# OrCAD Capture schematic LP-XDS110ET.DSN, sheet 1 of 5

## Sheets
1 1_Debugger Interface: size A3; title: LP-XDS110ET; rev: B; company: Texas Instruments
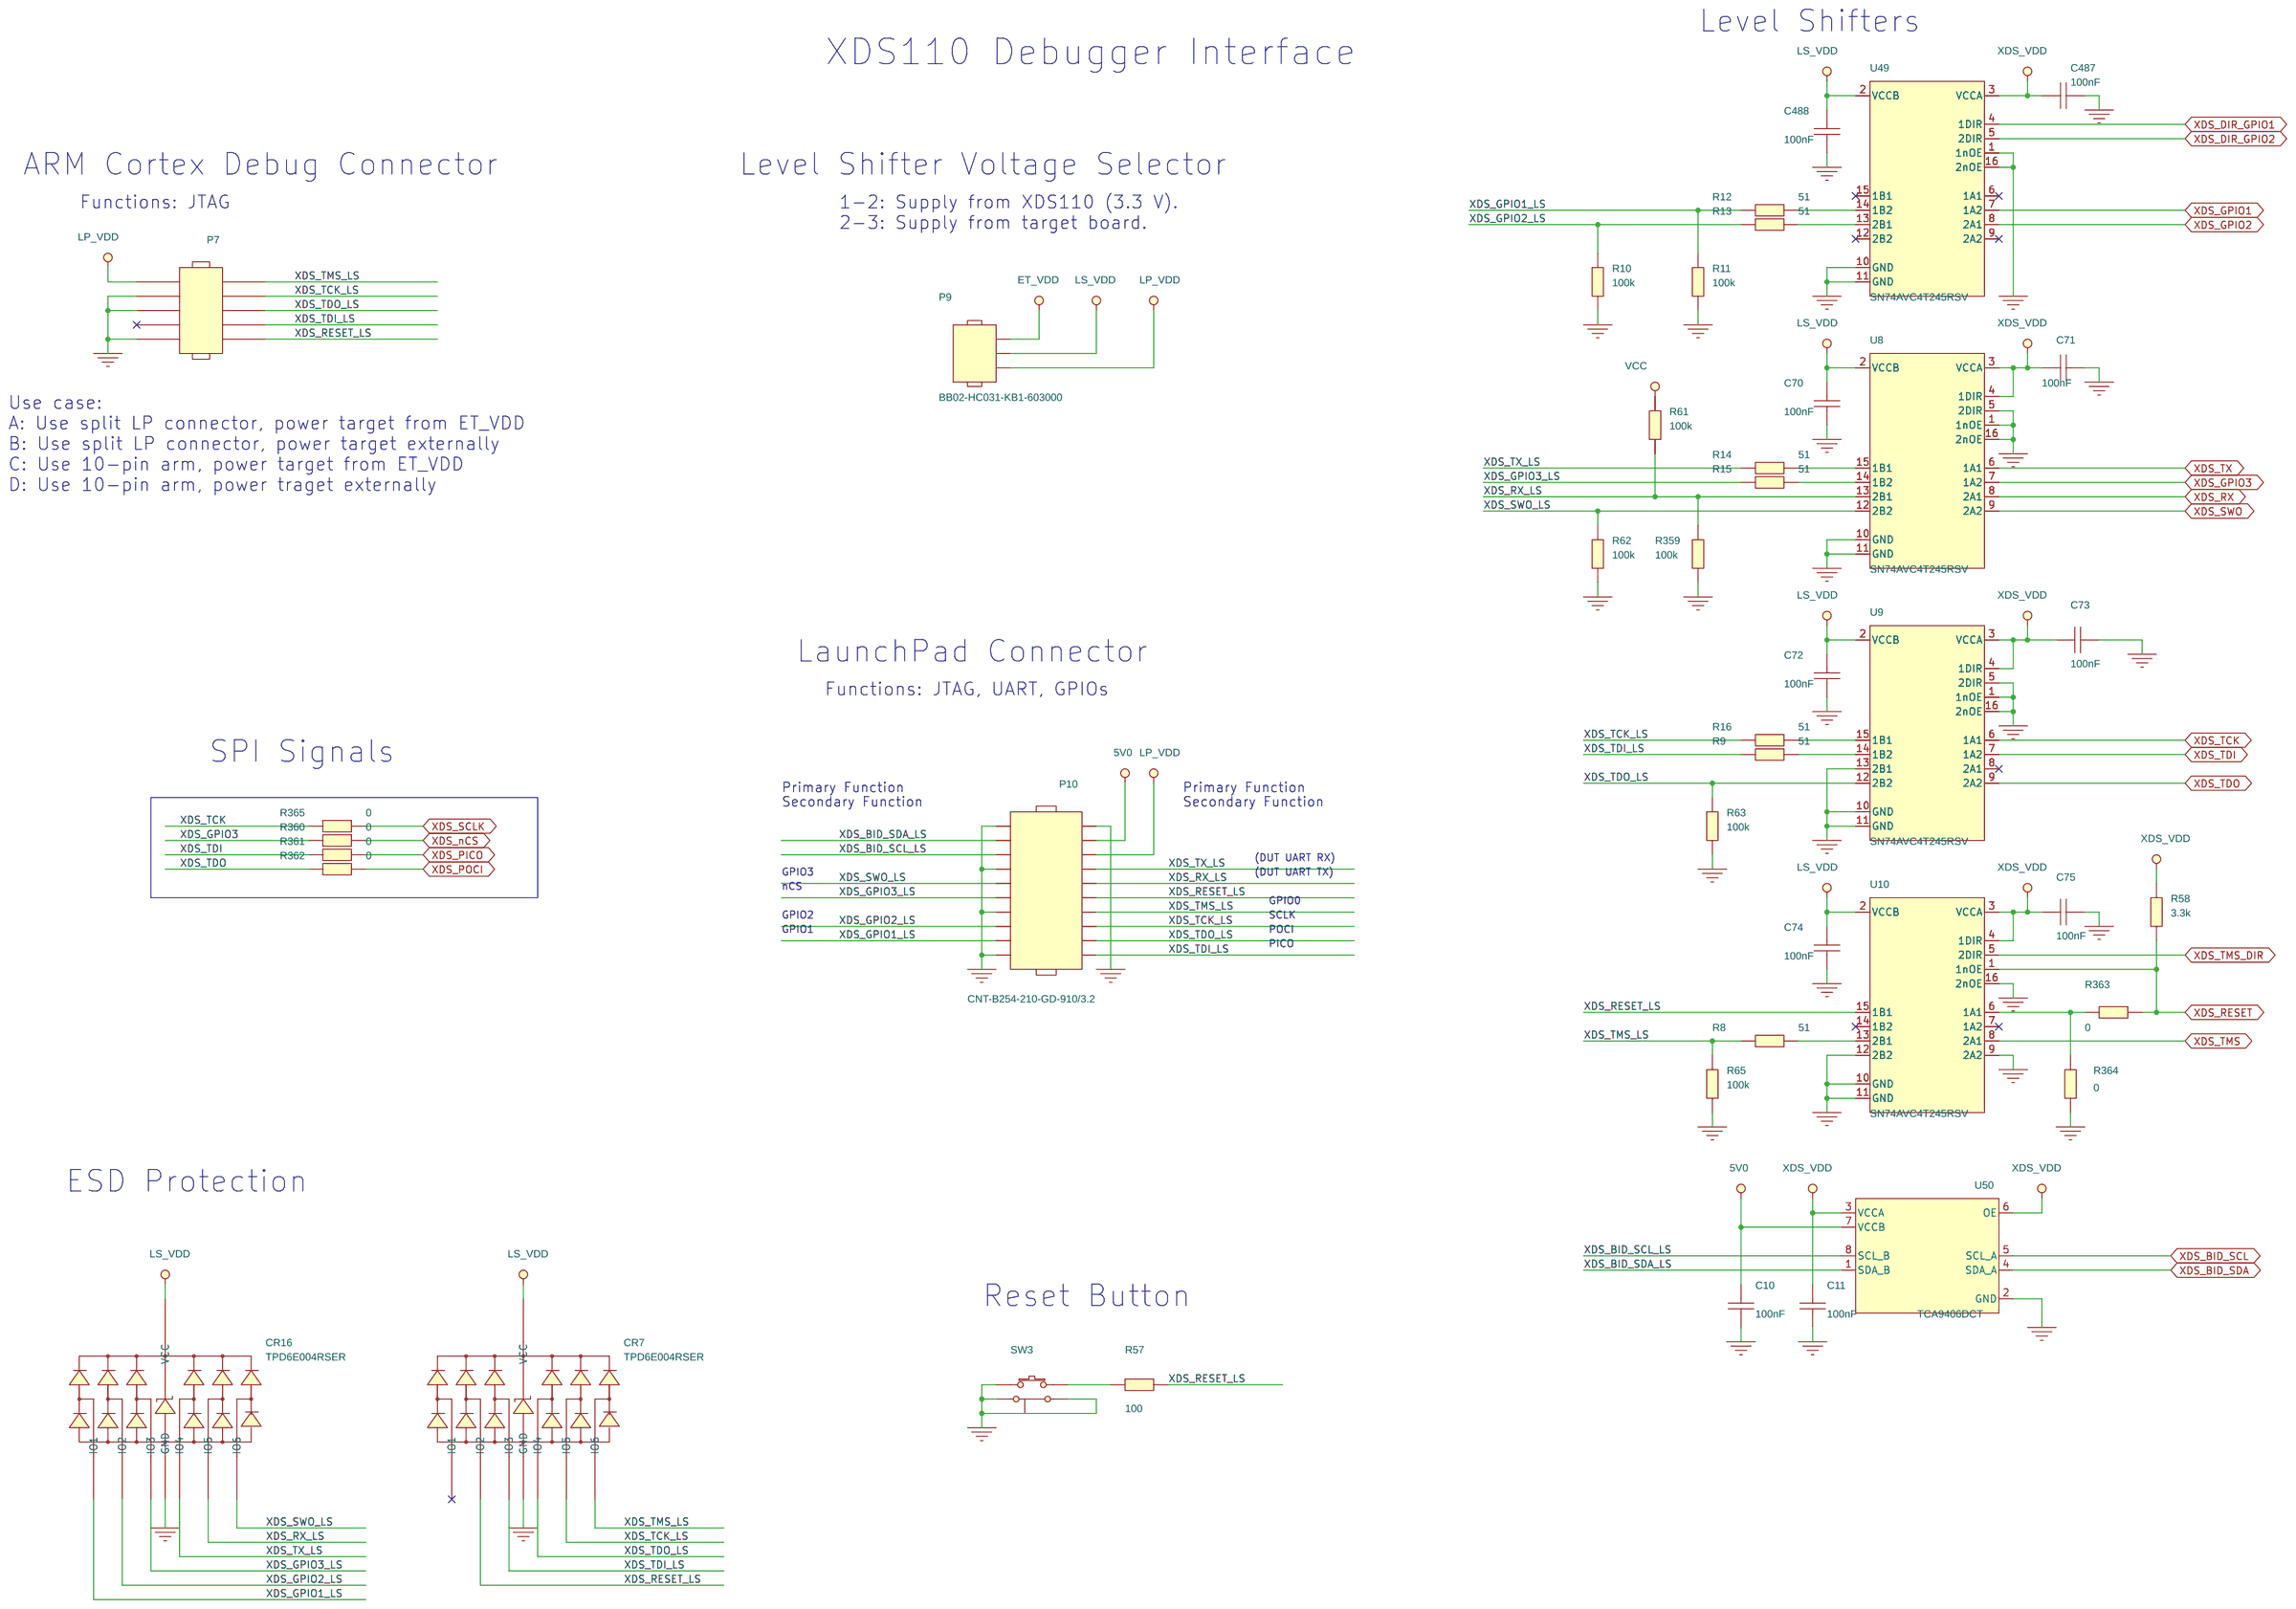
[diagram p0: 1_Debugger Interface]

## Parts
C10  100nF  [CAPC0603X35B2N]
C11  100nF  [CAPC0603X35B2N]
C70  100nF  [CAPC0603X35B2N]
C71  100nF  [CAPC0603X35B2N]
C72  100nF  [CAPC0603X35B2N]
C73  100nF  [CAPC0603X35B2N]
C74  100nF  [CAPC0603X35B2N]
C75  100nF  [CAPC0603X35B2N]
C487  100nF  [CAPC0603X35B2N]
C488  100nF  [CAPC0603X35B2N]
CR7  TPD6E004RSER  [QFN50P150X150X60-8N]
CR16  TPD6E004RSER  [QFN50P150X150X60-8N]
P7  FTSH-105-01-F-DV-K  [SAMTEC_FTSH-105-01-F-DV-K-10L]
P9  BB02-HC031-KB1-603000  [GRADCONN_BB02HC031KB1603000_A2B]
P10  CNT-B254-210-GD-910/3.2  [CNT_CNTB254210GD91032_A2B]
R8  51  [RESC0603X35B2N]
R9  51  [RESC0603X35B2N]
R10  100k  [RESC1005X40B2N]
R11  100k  [RESC1005X40B2N]
R12  51  [RESC0603X35B2N]
R13  51  [RESC0603X35B2N]
R14  51  [RESC0603X35B2N]
R15  51  [RESC0603X35B2N]
R16  51  [RESC0603X35B2N]
R57  100  [RESC1005X40B2N]
R58  3.3k  [RESC1005X40B2N]
R61  100k  [RESC1005X40B2N]
R62  100k  [RESC1005X40B2N]
R63  100k  [RESC1005X40B2N]
R65  100k  [RESC1005X40B2N]
R359  100k  [RESC1005X40B2N]
R360  0  [RESC1005X40B2N]
R361  0  [RESC1005X40B2N]
R362  0  [RESC1005X40B2N]
R363  0  [RESC1005X40B2N]
R364  0  [RESC1005X40B2N]
R365  0  [RESC1005X40B2N]
SW3  1188E-1K2  [SW_1188E1K2V_A2N]
U8  SN74AVC4T245RSV  [QFNFC40P180X260X55-16A2N]
U9  SN74AVC4T245RSV  [QFNFC40P180X260X55-16A2N]
U10  SN74AVC4T245RSV  [QFNFC40P180X260X55-16A2N]
U49  SN74AVC4T245RSV  [QFNFC40P180X260X55-16A2N]
U50  TCA9406DCT  [SOP65P400X130-8A2N]

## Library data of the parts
C10 C11 C70-C75 C487 C488 = CAPACITOR: CAPACITOR, CERAMIC X5R, 100nF, 10V, -10%/+10%, -55DEGC/+85DEGC, 0201, SMD; ALT_SYMBOLS: CAPC0603X35B2L,CAPC0603X35B2M; Additional Datasheet URL: http://psearch.en.murata.com/capacitor/product/GRM033R61A104KE84%23.html; AutoDoc File: https://notefied-dynamic-precision.com/DB/Apps/Desktop/Item/Object.aspx?id=96679; BU Name: DYNAMIC PRECISION GDANSK; Budget Currency: EUR; Budget Price: 0.008; Budgetary Price: 0.008 EUR; Client Status: UNDER_REVIEW; Country of Origin: Missing Info; Datasheet URL: http://psearch.murata.com/capacitor/product/GRM033R61A104KE84%23.pdf; Datasheet URL 1: http://psearch.murata.com/capacitor/product/GRM033R61A104KE84%23.pdf; Datasheet URL 2: http://search.murata.co.jp/Ceramy/image/img/w_hinm/L0005E.pdf; Dielectric Type: X5R; Lead Time: 17; LifeCycle Status: ACTIVE; MPN: GRM155R70J104KA01D; MPN Status: ACTIVE; Manufacturer: MURATA; Mass: 0.00033g; Max Oper Temp: +85DEGC; Max Tol: +10%; Maximum Operating Temperature: +85DEGC; Maximum Tolerance: +10%; Min Oper Temp: -55DEGC; Min Tol: -10%; Minimum Operating Temperature: -55DEGC; Minimum Tolerance: -10%; Mounting Type: SMD; NOTE Status: PREFERRED; NOTEfied URL: https://notefied-dynamic-precision.com/NOTEfiedWebInterface/part/show?partNumber=02-06085; Old Footprint: CAPC1005X60N,0402; PCB Package: 0201; Packing Size: 15000; Packing Type: Tape & Reel; Part Number: 02-06085; Part Type: Capacitor|CERAMIC|0201|STANDARD; REACH/SVHC Compliance: Compliant; REACH/SVHC Details: SVHC List Version Jul 7, 2017; REACH/SVHC Source: REACH Declaration; REACH/SVHC Status: Unaffected; REACH/SVHC_COMPLIANCE: COMPLIANT; REACH/SVHC_DETAILS: SVHC LIST VERSION Jun 20, 2016; REACH/SVHC_SOURCE: REACH DECLARATION; REACH/SVHC_STATUS: UNAFFECTED; ROHS: Compliant; Rated Voltage: 10V; Revision: R011; RoHS Status: ROHS_COMPLIANT; Rtd Voltage: 10V; Status: Released; Texas Part Status: Under Review; Type: Capacitor; Vendor: MURATA; Vendor Part Number: GRM033R61A104KE84D; Vendor Part Status: Active; WEIGHT: 0.00033g
CR7 CR16 = DIODE_TVS_TPD6E004_QFN8_V1: DIODE, PROTECTION, ESD ARRAY - 6 CHANNELS, 7V, -40DEGC/+85DEGC, QFN8, SMD; ALT_SYMBOLS: QFN50P150X150X60-8L,QFN50P150X150X60-8M; Additional Datasheet URL: http://www.ti.com/litv/pdf/mpqf207d; AutoDoc File: https://notefied-dynamic-precision.com/DB/Apps/Desktop/Item/Object.aspx?id=74721; BU Name: DYNAMIC PRECISION GDANSK; Budget Currency: USD; Budget Price: 0.27; Budgetary Price: 0.27 USD; CLASS: IC; Client Status: UNDER_REVIEW; Country of Origin: United States; Datasheet URL: http://www.ti.com/lit/ds/symlink/tpd6e004.pdf; Datasheet URL 1: http://www.ti.com/lit/ds/symlink/tpd6e004.pdf; Datasheet URL 2: http://www.ti.com/litv/pdf/mpqf207b; FPLIST: QFN50P150X150X60-8N,QFN50P150X150X60-8AN; Lead Time: 2; Mass: 0.0033g; Max Oper Temp: +85DEGC; Maximum Operating Temperature: +85DEGC; Min Oper Temp: -40DEGC; Minimum Operating Temperature: -40DEGC; Mounting Type: SMD; NOTEfied URL: https://notefied-dynamic-precision.com/NOTEfiedWebInterface/part/show?partNumber=14-05493; PCB Package: QFN8; Packing Size: 3000; Packing Type: Tape & Reel; Part Number: 14-05493; Part Type: Diode|PROTECTION; REACH/SVHC Compliance: Compliant; REACH/SVHC Details: SVHC List Version Jun 20, 2016; REACH/SVHC Source: Material Declaration; REACH/SVHC Status: Unaffected; ROHS: Compliant; Rated Power: N/A; Rated Voltage: 7V; Revision: R006; RoHS Status: ROHS_COMPLIANT; Rtd Power: N/A; Rtd Voltage: 7V; Status: Released; Texas Part Status: Under Review; Type: Diode; Vendor: TEXAS INSTRUMENTS; Vendor Part Status: Active; Weight: 0.0033g
P7 = CONN_HEADER_2X5: CONNECTOR, HEADER, MALE, STRAIGHT, 2 ROWS, 10 PINS, PITCH 1.27mm, SMD; ALT_SYMBOLS: SAMTEC_FTSH10501FDVK_A2L,SAMTEC_FTSH10501FDVK_A2M; Additional Datasheet URL: http://suddendocs.samtec.com/prints/ftsh-1xx-xx-xxx-dv-xxx-xxx-mkt.pdf; AutoDoc File: http://notefied-dynamic-precision.com/DB/Apps/Desktop/Item/Object.aspx?id=50836; Budget Currency: USD; Budget Price: 1.700; Budgetary Price: 1.7 USD; CLASS: IO; Country of Origin: China,Costa Rica,Malaysia,Singapore,United States; Datasheet URL: http://suddendocs.samtec.com/catalog_english/ftsh_smt.pdf; Datasheet URL 1: http://www.samtec.com/documents/webfiles/cpdf/FTSH-1XX-XX-XXX-DV-XXX-MKT.pdf; Datasheet URL 2: http://www.samtec.com/documents/webfiles/pdf/FTSH_SMT.PDF; FPLIST: SAMTEC_FTSH-105-01-F-DV-K-10N,SAMTEC_FTSH-105-01-F-DV-K-10L,SAMTEC_FTSH-105-01-F-DV-K-10M; Lead Time: 2; LifeCycle Status: MATURITY; MPN Status: ACTIVE; Manufacturer: SAMTEC; Mass: 0.65614g; Max Oper Temp: +125DEGC; Maximum Operating Temperature: +125DEGC; Min Oper Temp: -55DEGC; Minimum Operating Temperature: -55DEGC; Mounting Type: SMD; NOTE Status: PREFERRED; NOTEfied URL: https://notefied-dynamic-precision.com/NOTEfiedWebInterface/part/show?partNumber=06-00166; No Of Pos: 10; No Of Rows: 2; Number of Positions: 10; Number of Rows: 2; Old Footprint: SAMTEC_FTSH-105-01-F-DV-K-10N,CONN_MALE_2X5; Packing Size: 92; Packing Type: Tube; Part Number: 06-00166; Part Type: Connector|HEADER|STANDARD; Pitch: 1.27mm; REACH/SVHC Compliance: Compliant; REACH/SVHC Details: SVHC List Version Jun 20, 2016; REACH/SVHC Source: Material Declaration; REACH/SVHC Status: Unaffected; ROHS: Compliant; Rated Current: 1.75A; Revision: R008; RoHS Status: ROHS_COMPLIANT; Rtd Current: 1.75A; Status: Released; Texas Part Status: Under Review; Type: Connector; Vendor: SAMTEC; Vendor Part Status: Active; WEIGHT: 0.65614g
P9 = CONN_HEADER_3_P_S: CONNECTOR, HEADER, MALE, STRAIGHT, 1 ROW, 3 PINS, PITCH 2.54mm, PTH; ALT_SYMBOLS: GRADCONN_BB02HC031KB1603000_A2C,GRADCONN_BB02HC031KB1603000_A2A; Additional Datasheet URL: https://www.gradconn.com/Files/Drawings/BB02-HC.pdf; Country of Origin: Missing Info; Datasheet URL: https://www.gradconn.com/Files/Specs/BTB-2.54mm-Header-specification.pdf; Mass: N/A; Maximum Operating Temperature: +105DEGC; Minimum Operating Temperature: -40DEGC; Mounting Type: PTH; NOTEfied URL: https://notefied-dynamic-precision.com/NOTEfiedWebInterface/part/show?partNumber=06-05038; Number of Positions: 3; Number of Rows: 1; Packing Size: N/A; Packing Type: Missing Info; Part Number: 06-05038; Part Type: Connector|HEADER|STANDARD; Pitch: 2.54mm; REACH/SVHC Compliance: Compliant; REACH/SVHC Details: SVHC List Version Jun 20, 2016; REACH/SVHC Source: RoHS & REACH Declaration; REACH/SVHC Status: Unaffected; ROHS: Compliant; Rated Current: 3A; Rated Voltage: 250V; Revision: R017; Status: Released; Texas Part Status: Under Review; Type: Connector; Vendor: GRADCONN; Vendor Part Status: Active
P10 = CONN_HEADER_2X10_P_V3: CONNECTOR, HEADER, SHROUDED, MALE, RIGHT ANGLE, 2 ROWS, 20 PINS, PITCH 2.54mm, PTH; ALT_SYMBOLS: CNT_CNTB254210GD91032_A2A,CNT_CNTB254210GD91032_A2C; Additional Datasheet URL: http://yccnt.com/cpzx/info_56.aspx?itemid=1242&lcid=3&cid=7; Datasheet URL: http://yccnt.com/uploadfiles/2017/08/201708261633563356.pdf; Maximum Operating Temperature: +105DEGC; Minimum Operating Temperature: -40DEGC; Mounting Type: PTH; NOTEfied URL: https://notefied-dynamic-precision.com/NOTEfiedWebInterface/part/show?partNumber=06-08436; Number of Positions: 20; Number of Rows: 2; Packing Size: N/A; Packing Type: Missing Info; Part Number: 06-08436; Part Type: Connector|HEADER|SHROUDED; Pitch: 2.54mm; REACH/SVHC Compliance: Missing Info; REACH/SVHC Details: N/A; REACH/SVHC Source: N/A; REACH/SVHC Status: Missing Info; ROHS: Compliant; Rated Current: 3A; Rated Voltage: 500V; Revision: R004; Status: Released; Texas Part Status: Under Review; Type: Connector; Vendor: CNT CONNECTORS; Vendor Part Status: Active
R8 R9 R12-R16 = RESISTOR: RESISTOR, THICK FILM, 51, -5%/+5%, 0.05W, 30V, -55DEGC/+155DEGC, 0201, SMD; ALT_SYMBOLS: RESC0603X35B2L,RESC0603X35B2M; Additional Datasheet URL: N/A; AutoDoc File: https://notefied-dynamic-precision.com/DB/Apps/Desktop/Item/Object.aspx?id=114554; BU Name: TEXAS INSTRUMENTS NORWAY; Budget Currency: EUR; Budget Price: 0.014; Budgetary Price: 0.0041 USD; Client Status: UNDER_REVIEW; Country of Origin: Taiwan; Datasheet URL: http://www.vishay.com/docs/20052/crcw0201e3.pdf; Datasheet URL 1: http://www.vishay.com/docs/20035/dcrcwe3.pdf; Datasheet URL 2: N/A; Definied Quality: INDUSTRIAL; Esd Level: N/A; Lead Time: 7; LifeCycle Status: ACTIVE; MPN: RESISTOR_0402_51_+/-5%_50V_0.063W_M_+/-200ppm; MPN Status: ACTIVE; MSL: N/A; MTBF: N/A; MTBF Standard: N/A; Manufacturer: MANUFACTURER SELECTION; Mass: 0.00017g; Max Oper Temp: +155DEGC; Max TC: +200PPM/DEGC; Max Tol: +5%; Maximum Operating Temperature: +155DEGC; Maximum Temperature Coefficient: +200PPM/DEGC; Maximum Tolerance: +5%; Min Oper Temp: -55DEGC; Min TC: -200PPM/DEGC; Min Tol: -5%; Minimum Operating Temperature: -55DEGC; Minimum Temperature Coeficient: -200PPM/DEGC; Minimum Tolerance: -5%; Mounting Type: SMD; NOTE Status: PREFERRED; NOTEfied URL: https://notefied-dynamic-precision.com/NOTEfiedWebInterface/part/show?partNumber=01-04141; Old Footprint: RESC1005X40N; PCB Package: 0201; Packing Size: 10000; Packing Type: Tape & Reel; Part Number: 01-04141; Part Type: Resistor|0201|STANDARD; REACH/SVHC_COMPLIANCE: COMPLIANT; REACH/SVHC_DETAILS: SVHC LIST VERSION Jun 20, 2016; REACH/SVHC_SOURCE: MATERIAL DECLARATION; REACH/SVHC_STATUS: UNAFFECTED; ROHS: Exempt; Rated Current: N/A; Rated Power: 0.05W; Rated Voltage: 30V; Resistor Type: THICK FILM; Revision: R004; RoHS Status: ROHS_COMPLIANT; Rtd Current: N/A; Rtd Power: 0.063W; Rtd Voltage: 50V; Status: Released; Type: Resistor; Vendor: VISHAY; Vendor Part Number: CRCW020151R0JNED; Vendor Part Status: Active; WEIGHT: 0.00065g
R10 R11 R61-R63 R65 R359 = RESISTOR: RESISTOR, THICK FILM, 100k, -1%/+1%, 0.063W, 50V, -55DEGC/+155DEGC, 0402, SMD; Additional Datasheet URL: http://www.ttelectronics.com/resistors/parts/wcr0402; AutoDoc File: https://notefied-dynamic-precision.com/DB/Apps/Desktop/Item/Object.aspx?id=115161; BU Name: TEXAS INSTRUMENTS NORWAY; Client Status: UNDER_REVIEW; Datasheet URL: http://www.ttelectronicsresistors.com/datasheets/WCR.pdf; Datasheet URL 1: http://www.ttelectronicsresistors.com/datasheets/WCR.pdf; Definied Quality: INDUSTRIAL; Esd Level: N/A; LifeCycle Status: ACTIVE; MPN: RESISTOR_0402_100k_+/-1%_50V_0.063W_M_+/-100PPM; MPN Status: ACTIVE; MSL: N/A; MTBF: N/A; MTBF Standard: N/A; Manufacturer: MANUFACTURER SELECTION; Max Oper Temp: +155DEGC; Max TC: +100PPM/DEGC; Max Tol: +1%; Maximum Operating Temperature: +155DEGC; Maximum Temperature Coefficient: +100PPM/DEGC; Maximum Tolerance: +1%; Min Oper Temp: -55DEGC; Min TC: -100PPM/DEGC; Min Tol: -1%; Minimum Operating Temperature: -55DEGC; Minimum Temperature Coeficient: -100PPM/DEGC; Minimum Tolerance: -1%; Mounting Type: SMD; NOTE Status: PREFERRED; NOTEfied URL: https://notefied-dynamic-precision.com/NOTEfiedWebInterface/part/show?partNumber=01-22536; Old Footprint: RESC1005X40N; PCB Package: 0402; Packing Size: 10000; Packing Type: Tape & Reel; Part Number: 01-22536; Part Type: Resistor|0402|PRECISION; REACH/SVHC Compliance: Compliant; REACH/SVHC Details: SVHC List Version Jun 20, 2016; REACH/SVHC Source: Material Declaration; REACH/SVHC Status: Unaffected; ROHS: Exempt; Rated Current: N/A; Rated Power: 0.063W; Rated Voltage: 50V; Resistor Type: THICK FILM; Revision: R007; RoHS Status: ROHS_COMPLIANT; Rtd Current: N/A; Rtd Power: 0.063W; Rtd Voltage: 50V; Status: Released; Texas Part Status: Under Review; Type: Resistor; Vendor: TT ELECTRONICS; Vendor Part Number: WCR0402-100KFA; Vendor Part Status: Active
R57 = RESISTOR: RESISTOR, THICK FILM, 100, -5%/+5%, 0.063W, 50V, -55DEGC/+155DEGC, 0402, SMD; Additional Datasheet URL: N/A; AutoDoc File: https://notefied-dynamic-precision.com/DB/Apps/Desktop/Item/Object.aspx?id=114555; BU Name: TEXAS INSTRUMENTS NORWAY; Budget Currency: USD; Budget Price: 0.0014; Budgetary Price: 0.0014 USD; Client Status: UNDER_REVIEW; Country of Origin: United States; Datasheet URL: http://www.vishay.com/docs/20035/dcrcwe3.pdf; Datasheet URL 1: http://www.vishay.com/docs/20035/dcrcwe3.pdf; Datasheet URL 2: N/A; Definied Quality: INDUSTRIAL; Esd Level: N/A; Exclusive for Customers: TEXAS INSTRUMENTS NORWAY; Lead Time: 16; LifeCycle Status: ACTIVE; MPN: RESISTOR_0402_100_+/-5%_50V_0.063W_M_+/-200ppm; MPN Status: ACTIVE; MSL: N/A; MTBF: N/A; MTBF Standard: N/A; Manufacturer: MANUFACTURER SELECTION; Mass: 0.00065g; Max Oper Temp: +155DEGC; Max TC: +200PPM/DEGC; Max Tol: +5%; Maximum Operating Temperature: +155DEGC; Maximum Temperature Coefficient: +200PPM/DEGC; Maximum Tolerance: +5%; Min Oper Temp: -55DEGC; Min TC: -200PPM/DEGC; Min Tol: -5%; Minimum Operating Temperature: -55DEGC; Minimum Temperature Coeficient: -200PPM/DEGC; Minimum Tolerance: -5%; Mounting Type: SMD; NOTE Status: PREFERRED; NOTEfied URL: https://notefied-dynamic-precision.com/NOTEfiedWebInterface/part/show?partNumber=01-22482; Notes: Standard item: Duplicate Reason: custom footprint for TEXAS INSTRUMENTS NORWAY.; Old Footprint: RESC1005X40N; PCB Package: 0402; Packing Size: 10000; Packing Type: Tape & Reel; Part Number: 01-22482; Part Type: Resistor|0402|STANDARD; REACH/SVHC Compliance: Compliant; REACH/SVHC Details: SVHC List Version Jun 20, 2016; REACH/SVHC Source: Material Declaration; REACH/SVHC Status: Unaffected; REACH/SVHC_COMPLIANCE: COMPLIANT; REACH/SVHC_DETAILS: SVHC LIST VERSION Jun 20, 2016; REACH/SVHC_SOURCE: MATERIAL DECLARATION; REACH/SVHC_STATUS: UNAFFECTED; ROHS: Exempt; Rated Current: N/A; Rated Power: 0.063W; Rated Voltage: 50V; Resistor Type: THICK FILM; Revision: R007; RoHS Status: ROHS_COMPLIANT; Rtd Current: N/A; Rtd Power: 0.063W; Rtd Voltage: 50V; Status: Released; Texas Part Status: Under Review; Type: Resistor; Vendor: VISHAY; Vendor Part Number: CRCW0402100RJNED; Vendor Part Status: Active; WEIGHT: 0.00065g
R58 = RESISTOR: RESISTOR, THICK FILM, 3.3k, -5%/+5%, 0.063W, 50V, -55DEGC/+155DEGC, 0402, SMD; Additional Datasheet URL: N/A; AutoDoc File: https://notefied-dynamic-precision.com/DB/Apps/Desktop/Item/Object.aspx?id=114561; BU Name: TEXAS INSTRUMENTS NORWAY; Budget Currency: EUR; Budget Price: 0.014; Budgetary Price: 0.014 EUR; Client Status: UNDER_REVIEW; Country of Origin: Israel; Datasheet URL: http://www.vishay.com/docs/20035/dcrcwe3.pdf; Datasheet URL 1: http://www.vishay.com/docs/20035/dcrcwe3.pdf; Datasheet URL 2: N/A; Definied Quality: INDUSTRIAL; Esd Level: N/A; Exclusive for Customers: TEXAS INSTRUMENTS NORWAY; Lead Time: 18; LifeCycle Status: ACTIVE; MPN: RESISTOR_0402_3.3k_+/-5%_50V_0.063W_M_+/-200ppm; MPN Status: ACTIVE; MSL: N/A; MTBF: N/A; MTBF Standard: N/A; Manufacturer: MANUFACTURER SELECTION; Mass: 0.00065g; Max Oper Temp: +155DEGC; Max TC: +200PPM/DEGC; Max Tol: +5%; Maximum Operating Temperature: +155DEGC; Maximum Temperature Coefficient: +200PPM/DEGC; Maximum Tolerance: +5%; Min Oper Temp: -55DEGC; Min TC: -200PPM/DEGC; Min Tol: -5%; Minimum Operating Temperature: -55DEGC; Minimum Temperature Coeficient: -200PPM/DEGC; Minimum Tolerance: -5%; Mounting Type: SMD; NOTE Status: PREFERRED; NOTEfied URL: https://notefied-dynamic-precision.com/NOTEfiedWebInterface/part/show?partNumber=01-22488; Notes: Standard item: Duplicate Reason: custom footprint for TEXAS INSTRUMENTS NORWAY.; Old Footprint: RESC1005X40N; PCB Package: 0402; Packing Size: 10000; Packing Type: Tape & Reel; Part Number: 01-22488; Part Type: Resistor|0402|STANDARD; REACH/SVHC Compliance: Compliant; REACH/SVHC Details: SVHC List Version Jun 20, 2016; REACH/SVHC Source: Material Declaration; REACH/SVHC Status: Unaffected; REACH/SVHC_COMPLIANCE: COMPLIANT; REACH/SVHC_DETAILS: SVHC LIST VERSION Jun 20, 2016; REACH/SVHC_SOURCE: MATERIAL DECLARATION; REACH/SVHC_STATUS: UNAFFECTED; ROHS: Exempt; Rated Current: N/A; Rated Power: 0.063W; Rated Voltage: 50V; Resistor Type: THICK FILM; Revision: R007; RoHS Status: ROHS_COMPLIANT; Rtd Current: N/A; Rtd Power: 0.063W; Rtd Voltage: 50V; Status: Released; Texas Part Status: Under Review; Type: Resistor; Vendor: VISHAY; Vendor Part Number: CRCW04023K30JNED; Vendor Part Status: Active; WEIGHT: 0.00065g
R360-R365 = RESISTOR: RESISTOR, THICK FILM, 0, 0.063W, 50V, -55DEGC/+155DEGC, 0402, SMD; Additional Datasheet URL: N/A; AutoDoc File: https://notefied-dynamic-precision.com/DB/Apps/Desktop/Item/Object.aspx?id=47959; BU Name: DYNAMIC PRECISION GDANSK; Budget Currency: EUR; Budget Price: 0.012; Budgetary Price: 0.007 EUR; Client Status: UNDER_REVIEW; Country of Origin: Israel; Datasheet URL: http://www.vishay.com/docs/20035/dcrcwe3.pdf; Datasheet URL 1: http://www.vishay.com/docs/20035/dcrcwe3.pdf; Datasheet URL 2: N/A; Exclusive for Customers: TEXAS INSTRUMENTS NORWAY; Lead Time: 14; Mass: 0.0006152g; Max Oper Temp: +155DEGC; Max TC: +100PPM/DEGC; Max Tol: +1%; Maximum Operating Temperature: +155DEGC; Maximum Temperature Coefficient: N/A; Maximum Tolerance: N/A; Min Oper Temp: -55DEGC; Min TC: -100PPM/DEGC; Min Tol: -1%; Minimum Operating Temperature: -55DEGC; Minimum Temperature Coeficient: N/A; Minimum Tolerance: N/A; Mounting Type: SMD; NOTEfied URL: https://notefied-dynamic-precision.com/NOTEfiedWebInterface/part/show?partNumber=01-22495; Notes: Standard item: Duplicate Reason: custom footprint for TEXAS INSTRUMENTS NORWAY.; PCB Package: 0402; Packing Size: 10000; Packing Type: Tape & Reel; Part Number: 01-22495; Part Type: Resistor|0402|JUMPER; REACH/SVHC Compliance: Compliant; REACH/SVHC Details: SVHC List Version Jul 07, 2017; REACH/SVHC Source: REACH Declaration; REACH/SVHC Status: Unaffected; ROHS: Exempt; Rated Current: N/A; Rated Power: 0.063W; Rated Voltage: 50V; Resistor Type: THICK FILM; Revision: R012; RoHS Status: ROHS_COMPLIANT_WITH_EXEMPTION; Rtd Current: N/A; Rtd Power: 0.063W; Rtd Voltage: 50V; Status: Released; Texas Part Status: Under Review; Type: Resistor; Vendor: VISHAY; Vendor Part Number: CRCW04020000Z0ED; Vendor Part Status: Active; Weight: 0.00060916g
SW3 = SWITCH_TACT_V2: SWITCH, TACT, 0.05A@12VDC, 0.05A@250VAC, SMD; ALT_SYMBOLS: SW_1188E1K2V_A2L,SW_1188E1K2V_A2M; Additional Datasheet URL: http://www.dip.com.tw/en/en-product-information/en-switch004/item/2445-1188; AutoDoc File: http://notefied-dynamic-precision.com/DB/Apps/Desktop/Item/Object.aspx?id=104642; CLASS: IC; Country of Origin: China,Vietnam; Datasheet URL: http://www.dip.com.tw/en/en-product-information/en-switch004/item/download/2483_bfc264bcfe9982a2b01570916dd931c3; Datasheet URL 1: N/A; Datasheet URL 2: http://www.dip.com.tw/en/en-product-information/en-switch004; FPLIST: SW_1188E1K2V_A2N,SW_1188E1K2V_A2L,SW_1188E1K2V_A2M; Lead Time: 12; MPN: 1188E-1K2-V-TR; MPN Status: ACTIVE; Manufacturer: DIPTRONICS; Mass: N/A; Max Oper Temp: +70DEGC; Maximum Operating Temperature: +70DEGC; Min Oper Temp: -25DEGC; Minimum Operating Temperature: -25DEGC; Mounting Type: SMD; NOTE Status: PREFERRED; NOTEfied URL: https://notefied-dynamic-precision.com/NOTEfiedWebInterface/part/show?partNumber=08-00293; Packing Size: 1500; Packing Type: Tape & Reel; Part Number: 08-00293; Part Type: Switch|TACTILE; REACH/SVHC Compliance: Compliant; REACH/SVHC Details: SVHC List Version Dec 17, 2015; REACH/SVHC Source: REACH Declaration; REACH/SVHC Status: Unaffected; ROHS: Compliant; Rated Current: 0.05A; Rated Voltage: 12VDC; Revision: R007; RoHS Status: ROHS_COMPLIANT; Rtd Current: 0.05A; Rtd Voltage: 12V; Status: Released; Texas Part Status: Under Review; Type: Switch; Vendor: DIPTRONICS; Vendor Part Number: 1188E-1K2-V-TR; Vendor Part Status: Active
U8-U10 U49 = IC_XCVR_SN74AVC4T245_UQFN16_2: IC, DIGITAL, LOGIC, 4bit DUAL-SUPPLY BUS TRANSCEIVER 3 STATE OUTPUT, 1.2V TO 3.6V, UQFN16, SMD; ALT_SYMBOLS: QFNFC40P180X260X55-16A2L,QFNFC40P180X260X55-16A2M; Additional Datasheet URL: http://www.ti.com/litv/pdf/mpqf205c; AutoDoc File: http://notefied-dynamic-precision.com/DB/Apps/Desktop/Item/Object.aspx?id=95718; Budget Currency: USD; Budget Price: 0.39; Budgetary Price: 0.39 USD; CLASS: IC; Country of Origin: China,Thailand; Datasheet URL: http://www.ti.com/lit/ds/symlink/sn74avc4t245.pdf; Datasheet URL 1: http://www.ti.com/litv/pdf/mpqf205c; Datasheet URL 2: http://www.ti.com/lit/ds/symlink/sn74avc4t245.pdf; Definied Quality: INDUSTRIAL; FPLIST: QFNFC40P180X260X55-16A2N,QFNFC40P180X260X55-16A2L,QFNFC40P180X260X55-16A2M; Lead Time: 8; LifeCycle Status: ACTIVE; MPN: SN74AVC4T245RSVR; MPN Status: ACTIVE; MSL: 1; Manufacturer: TEXAS INSTRUMENTS; Mass: 0.0061g; Max Oper Temp: +85DEGC; Maximum Operating Temperature: +85DEGC; Min Oper Temp: -40DEGC; Minimum Operating Temperature: -40DEGC; Mounting Type: SMD; NOTE Status: PREFERRED; NOTEfied URL: https://notefied-dynamic-precision.com/NOTEfiedWebInterface/part/show?partNumber=18-29288; PCB Package: UQFN16; Packing Size: 3000; Packing Type: Tape & Reel; Part Number: 18-29288; Part Type: IC|DIGITAL|LOGIC|TRANSCEIVER; REACH/SVHC Compliance: Compliant; REACH/SVHC Details: SVHC List Version Jun 20, 2016; REACH/SVHC Source: Material Declaration; REACH/SVHC Status: Unaffected; ROHS: Compliant; Rated Voltage: 1.2V TO 3.6V; Revision: R009; RoHS Status: ROHS_COMPLIANT; Rtd Voltage: 1.2V TO 3.6V; Status: Released; Texas Part Status: Under Review; Type: IC; Vendor: TEXAS INSTRUMENTS; Vendor Part Number: SN74AVC4T245RSVR; Vendor Part Status: Active; WEIGHT: 0.0062g
U50 = IC_PERIPH_TCA9406_SM8: IC, DIGITAL, 2-BIT BIDIRECTIONAL 1MHz I2C / SMBUS VOLTAGE LEVEL-TRANSLATOR, VCCA:1.65V TO 3.6V, VCCB:2.3V TO 5.5V, SM8, SMD; ALT_SYMBOLS: SOP65P400X130-8A2L,SOP65P400X130-8A2M; Additional Datasheet URL: https://www.ti.com/lit/pdf/mpds049c; Budgetary Price: 0.268 USD; Datasheet URL: https://www.ti.com/lit/ds/symlink/tca9406.pdf; Mass: 0.062384575g; Maximum Operating Temperature: +85DEGC; Minimum Operating Temperature: -40DEGC; Mounting Type: SMD; NOTEfied URL: https://notefied-dynamic-precision.com/NOTEfiedWebInterface/part/show?partNumber=18-36685; PCB Package: SM8; Packing Size: 3000; Packing Type: Tape & Reel; Part Number: 18-36685; Part Type: IC|DIGITAL|LOGIC|LEV TRANSLATOR; REACH/SVHC Compliance: Compliant; REACH/SVHC Details: SVHC List Version Jan 19, 2021; REACH/SVHC Source: Material Declaration; REACH/SVHC Status: Unaffected; ROHS: Compliant; Rated Voltage: 1.65V TO 3.6V / 2.3V TO 5.5V; Revision: R001; Status: Released; Texas Part Status: Under Review; Type: IC; Vendor: TEXAS INSTRUMENTS; Vendor Part Number: TCA9406DCTR; Vendor Part Status: Active

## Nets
5V0: C10.1 P10.3 U50.7(VCCB) ; also on sheet 2 4
GND: C10.2 C11.2 C70.2 C71.2 C72.2 C73.2 C74.2 C75.2 C487.2 C488.2 CR7.4(GND) CR16.4(GND) P7.3 P7.5 P7.9 P10.1 P10.2 P10.8 P10.14 P10.20 R10.1 R11.1 R62.1 R63.1 R65.1 R359.1 R364.2 SW3.1 SW3.2 SW3.4 U8.1(1nOE) U8.5(2DIR) U8.10(GND) U8.11(GND) U8.16(2nOE) U9.1(1nOE) U9.5(2DIR) U9.10(GND) U9.11(GND) U9.13(2B1) U9.16(2nOE) U10.9(2A2) U10.10(GND) U10.11(GND) U10.12(2B2) U10.16(2nOE) U49.1(1nOE) U49.10(GND) U49.11(GND) U49.16(2nOE) U50.2(GND) ; also on sheet 2 3 4 5
ET_VDD: P9.1 ; also on sheet 4
LP_VDD: P7.1 P9.3 P10.5 ; also on sheet 3
LS_VDD: C70.1 C72.1 C74.1 C488.1 CR7.8(VCC) CR16.8(VCC) P9.2 R61.2 U8.2(VCCB) U9.2(VCCB) U10.2(VCCB) U49.2(VCCB) ; also on sheet 3
XDS_BID_SCL: U50.5(SCL_A) ; also on sheet 2
XDS_BID_SCL_LS: P10.6 U50.8(SCL_B)
XDS_BID_SDA: U50.4(SDA_A) ; also on sheet 2
XDS_BID_SDA_LS: P10.4 U50.1(SDA_B)
XDS_DIR_GPIO1: U49.4(1DIR) ; also on sheet 2
XDS_DIR_GPIO2: U49.5(2DIR) ; also on sheet 2
XDS_GPIO1: U49.7(1A2) ; also on sheet 2
XDS_GPIO1_LS: CR16.1(IO1) P10.18 R11.2 R12.1
XDS_GPIO2: U49.8(2A1) ; also on sheet 2
XDS_GPIO2_LS: CR16.2(IO2) P10.16 R10.2 R13.1
XDS_GPIO3: R360.2 U8.7(1A2) ; also on sheet 2
XDS_GPIO3_LS: CR16.3(IO3) P10.12 R15.1
XDS_nCS: R360.1 ; also on sheet 2
XDS_PICO: R361.1 ; also on sheet 2
XDS_POCI: R362.1 ; also on sheet 2
XDS_RESET: R58.1 R363.1 U10.1(1nOE) ; also on sheet 2
XDS_RESET_LS: CR7.2(IO2) P7.10 P10.11 R57.1 U10.15(1B1)
XDS_RX: U8.8(2A1) ; also on sheet 2
XDS_RX_LS: CR16.6(IO5) P10.9 R61.1 R359.2 U8.13(2B1)
XDS_SCLK: R365.1 ; also on sheet 2
XDS_SWO: U8.9(2A2) ; also on sheet 2
XDS_SWO_LS: CR16.7(IO6) P10.10 R62.2 U8.12(2B2)
XDS_TCK: R365.2 U9.6(1A1) ; also on sheet 2
XDS_TCK_LS: CR7.6(IO5) P7.4 P10.15 R16.1
XDS_TDI: R361.2 U9.7(1A2) ; also on sheet 2
XDS_TDI_LS: CR7.3(IO3) P7.8 P10.19 R9.1
XDS_TDO: R362.2 U9.9(2A2) ; also on sheet 2
XDS_TDO_LS: CR7.5(IO4) P7.6 P10.17 R63.2 U9.12(2B2)
XDS_TMS: U10.8(2A1) ; also on sheet 2
XDS_TMS_DIR: U10.5(2DIR) ; also on sheet 2
XDS_TMS_LS: CR7.7(IO6) P7.2 P10.13 R8.1 R65.2
XDS_TX: U8.6(1A1) ; also on sheet 2
XDS_TX_LS: CR16.5(IO4) P10.7 R14.1
XDS_VDD: C11.1 C71.1 C73.1 C75.1 C487.1 R58.2 U8.3(VCCA) U8.4(1DIR) U9.3(VCCA) U9.4(1DIR) U10.3(VCCA) U10.4(1DIR) U49.3(VCCA) U50.3(VCCA) U50.6(OE) ; also on sheet 2
N2777344: R57.2 SW3.3
N3267387: R14.2 U8.15(1B1)
N3267505: R9.2 U9.14(1B2)
N3267702: R8.2 U10.13(2B1)
N3268107: R12.2 U49.14(1B2)
N3268153: R13.2 U49.13(2B1)
N3268969: R15.2 U8.14(1B2)
N3455582: R363.2 R364.1 U10.6(1A1)
N3465637: R16.2 U9.15(1B1)

Not connected (* = marked no-connect by the designer): CR7 1(IO1)*; P7 7*; U9 8(2A1)*; U10 7(1A2)* 14(1B2)*; U49 6(1A1)* 9(2A2)* 12(2B2)* 15(1B1)*

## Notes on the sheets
sheet 1
- Level Shifters
- XDS110 Debugger Interface
- ARM Cortex Debug Connector
- Level Shifter Voltage Selector
- Functions: JTAG
- 1-2: Supply from XDS110 (3.3 V).
  2-3: Supply from target board.
- Use case:
  A: Use split LP connector, power target from ET_VDD
  B: Use split LP connector, power target externally
  C: Use 10-pin arm, power target from ET_VDD
  D: Use 10-pin arm, power traget externally
- LaunchPad Connector
- Functions: JTAG, UART, GPIOs
- SPI Signals
- Primary Function
- Primary Function
- Secondary Function
- Secondary Function
- (DUT UART RX)
- GPIO3
- (DUT UART TX)
- nCS
- GPIO2
- GPIO0
- SCLK
- GPIO1
- POCI
- PICO
- ESD Protection
- Reset Button
